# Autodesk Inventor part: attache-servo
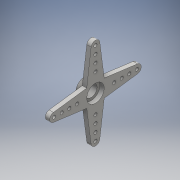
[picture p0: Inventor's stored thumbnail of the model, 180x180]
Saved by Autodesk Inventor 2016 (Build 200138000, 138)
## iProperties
Created: 2016-03
Part Number: attache-servo
Material: Generic
Document SubType Name: Modeling
Designer: Administrateur
Density: 1 g/cm^3
Appearance: Default
Author: Administrateur
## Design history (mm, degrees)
sketch "Esquisse1"
  geometry: C1 r 2.75 at (0, 0); C2 r 4 at (0, 0); 1 further point
  constraints: 2 centre point, 2 coincident
  dimensions: "d0" = 5.5 diameter of C1; "d1" = 8 diameter of C2
extrude "Extrusion1" new body sketch "Esquisse1" distance "d2" = 3; taper "d3" = 0 deg
sketch "Esquisse2" dims "d14" = 10
  geometry: L1 (0, 0)-(0, 34.263); L2 (-4, 4)-(4, 4); L3 (-4, 4)-(-1.983, 19.262); L4 (1.983, 19.262)-(4, 4); L5 (0, -3.5)-(0, 30.763); L6 (0, -7)-(0, 27.263); L7 (0, -10.5)-(0, 23.763); L8 (-4, 0)-(-4, 4); L9 (4, 0)-(4, 4); C1 r 0.75 at (0, 19); C2 r 0.75 at (0, 15.5); C3 r 0.75 at (0, 12); C4 r 0.75 at (0, 8.5); A1 r 2 centre (0, 19) between (1.983, 19.262) and (-1.983, 19.262); A2 r 4 centre (0, 0) between (-4, 0) and (4, 0) reference; A3 r 4 centre (0, 0) between (-4, 0) and (4, 0) reference; 3 further points
  constraints: 18 end point, 6 point on circle, 5 centre point, 5 point on line, 5 tangent, 4 coincident, 2 vertical, 1 collinear, 1 perpendicular, 17 other
  dimensions: "d4" = 4 distance from line of L1 L2.end; "d5" = 4 distance from line of L1 L2.start; "d6" = 2 radius of A1; "d7" = 19 distance of A1.centre L1.start; "d8" = 1.5 diameter of C1; "d11" = 3.5 distance of L1.start L5.start
extrude "Extrusion2" join sketch "Esquisse2" distance "d16" = 2; taper "d17" = 0 deg
pattern_circular "Réseau circulaire1" dims angle "d19" = 360 deg
node "Solide1"
